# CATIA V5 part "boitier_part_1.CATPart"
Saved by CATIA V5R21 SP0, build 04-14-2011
Part number: boitier_part_1
Bounding box of the stored display mesh (mm): x -44.5 to 44.5, y -30 to 30, z 0 to 34.5
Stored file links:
  C:\Users\zerma\Pictures\CAO\boitier_part_1.CATPart
  C:\Users\zerma\Pictures\CAO\Boitier batterie 5V.CATProduct
  C:\Users\zerma\Pictures\CAO\boitier_part_2.CATPart
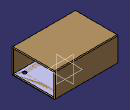
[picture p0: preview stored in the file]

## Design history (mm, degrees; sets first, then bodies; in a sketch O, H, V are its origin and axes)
Set1
  DatumCurve1: linked copy from another document
  DatumCurve2: linked copy from another document
Body1 (main body)
  Sketch1 on xy-plane, origin (0, 0, 0), H (1, 0, 0), V (0, 1, 0)
    line L1 (-44.5, 30) -> (44.5, 30)
    line L2 (44.5, 30) -> (44.5, -30)
    line L3 (44.5, -30) -> (-44.5, -30)
    line L4 (-44.5, -30) -> (-44.5, 30)
    circle A1 centre (34.4, 21.9) radius 2.5
    point P5 (34.4, 21.9)
    circle A2 centre (-34.4, 21.9) radius 2.5
    circle A3 centre (34.4, -21.9) radius 2.5
    circle A4 centre (-34.4, -21.9) radius 2.5
    length L1 = 89
    length L2 = 60
    radius A1 = 2.5
    distance P5 V = 34.4
    distance P5 H = 21.9
    horizontal: L1 H, L3 H
    vertical: L2 V, L4 V
    symmetry: L3 L1 H, L2 L4 V, A1 A2 V, A1 A3 H, A3 A4 V
  Pad1: profile Sketch1, direction (0, 0, 1), length 2.5
  Sketch2 on end face of Pad1, origin (0, 0, 2.5), H (1, 0, 0), V (0, 1, 0)
    line L1 (44.5, -28) -> (-42.5, -28)
    line L2 (-42.5, -28) -> (-42.5, 28)
    line L3 (-42.5, 28) -> (44.5, 28)
    point P1 (44.5, 28)
    point P2 (44.5, -28)
    line L4 (44.5, -30) -> (-44.5, -30)
    line L5 (-44.5, -30) -> (-44.5, 30)
    line L6 (-44.5, 30) -> (44.5, 30)
    reference projected line E1 (-44.5, -30) -> (44.5, -30) from edge [face of Pad1 from Sketch1.L3 | end face of Pad1]
    reference projected line E2 (44.5, -30) -> (44.5, 30) from edge [face of Pad1 from Sketch1.L2 | end face of Pad1]
    reference projected line E3 (44.5, -30) -> (44.5, 30) from edge [face of Pad1 from Sketch1.L2 | end face of Pad1]
    line L7 (44.5, 30) -> (44.5, 28)
    line L8 (44.5, -28) -> (44.5, -30)
    reference projected line E4 (-44.5, 30) -> (-44.5, -30) from edge [face of Pad1 from Sketch1.L4 | end face of Pad1]
    length L7 = 2
    distance L5 E4 = 0
    distance L2 L5 = 2
    horizontal: L1 H, L3 H, L4 H, L6 H
    vertical: L2 V, L5 V
    equidistance: L1 L3 O, L4 L6 O
    coincidence: L4 E1, P1 E2, P2 E3
  Pad2: profile Sketch2, direction (0, 0, 1), length 32
  Sketch3 on face of Pad2 from Sketch2.L2, origin (-42.5, 0, 0), H (0, 1, 0), V (0, 0, 1)
    line L1 (-28, 34.5) -> (28, 34.5)
    line L2 (28, 34.5) -> (28, 32.5)
    line L3 (28, 32.5) -> (-28, 32.5)
    line L4 (-28, 32.5) -> (-28, 34.5)
    reference projected line E1 (-28, 34.5) -> (28, 34.5) from edge [face of Pad2 from Sketch2.L2 | end face of Pad2]
    reference projected line E2 (-28, 2.5) -> (-28, 34.5) from edge [face of Pad2 from Sketch2.L1 | face of Pad2]
    reference projected line E3 (28, 2.5) -> (28, 34.5) from edge [face of Pad2 | face of Pad2 from Sketch2.L3]
    distance L3 L1 = 2
    horizontal: L1 H, L3 H
    vertical: L2 V, L4 V
    coincidence: L1 E1, L4 E2, L2 E3
  Pad3: profile Sketch3, direction (1, 0, 0), up to face of Pad2
  Chamfer1: length 1.5, angle 60, on edge [face of Pad1 from Sketch1.A3 | start face of Pad1]; edge [face of Pad1 from Sketch1.A1 | start face of Pad1]; edge [face of Pad1 from Sketch1.A2 | start face of Pad1]; edge [face of Pad1 from Sketch1.A4 | start face of Pad1]
  Sketch4 on face of Pad2, origin (-44.5, 0, 0), H (0, -1, 0), V (0, 0, 1)
    line L1 (-10, 22) -> (10, 22)
    line L2 (10, 22) -> (10, 9)
    line L3 (10, 9) -> (-10, 9)
    line L4 (-10, 9) -> (-10, 22)
    length L1 = 20
    distance L3 H = 9
    length L2 = 13
    horizontal: L1 H, L3 H
    vertical: L2 V, L4 V
    symmetry: L4 L2 V
  Pocket1: profile Sketch4, direction (1, 0, 0), length 28
  Chamfer2: length 1, angle 45, on edge [face of Pad2 | face of Pad2] (x7); edge [start face of Pad1 | face of Pad2] (x2); edge [face of Pad2 | face of Pad2 from Sketch2.L3]; edge [face of Pad2 | face of Pad3 from Sketch3.L3]; face of Pad2 (x2)
  CLDGeom1 "Maillage.1"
